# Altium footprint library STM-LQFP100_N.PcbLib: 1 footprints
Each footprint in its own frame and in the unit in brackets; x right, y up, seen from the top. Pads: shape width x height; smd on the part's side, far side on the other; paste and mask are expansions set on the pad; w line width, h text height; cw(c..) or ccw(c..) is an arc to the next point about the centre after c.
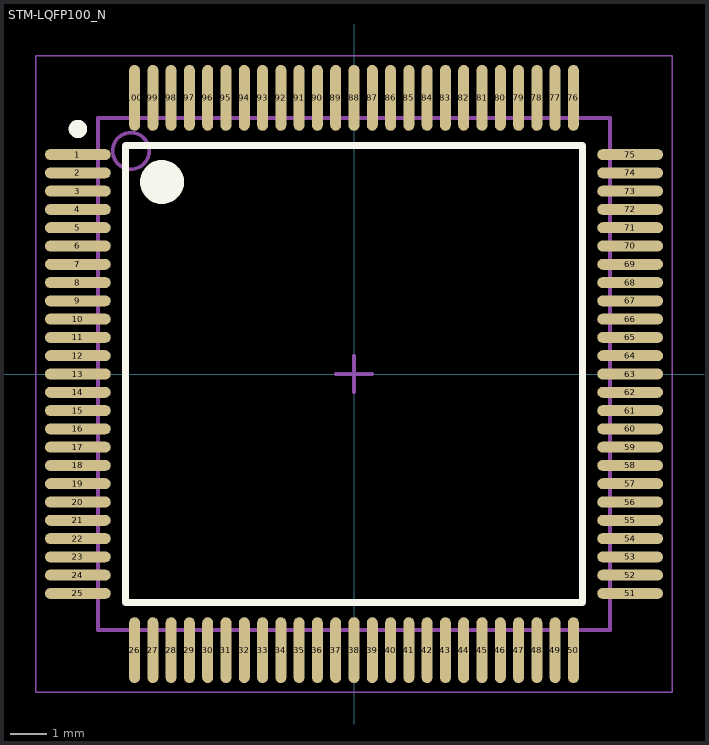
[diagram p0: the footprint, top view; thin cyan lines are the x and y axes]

## STM-LQFP100_N [mm] "Thin QFP, 100-Leads, Body 14x14mm, Pitch 0.5mm, IPC Medium Density"
height 1.6
pads (100):
  oval 1.8x0.3 smd: 1(-7.55,6) 2(-7.55,5.5) 3(-7.55,5) 4(-7.55,4.5) 5(-7.55,4) 6(-7.55,3.5) 7(-7.55,3) 8(-7.55,2.5) 9(-7.55,2) 10(-7.55,1.5) 11(-7.55,1) 12(-7.55,0.5) 13(-7.55,0) 14(-7.55,-0.5) 15(-7.55,-1) 16(-7.55,-1.5) 17(-7.55,-2) 18(-7.55,-2.5) 19(-7.55,-3) 20(-7.55,-3.5) 21(-7.55,-4) 22(-7.55,-4.5) 23(-7.55,-5) 24(-7.55,-5.5) 25(-7.55,-6) 51(7.55,-6) 52(7.55,-5.5) 53(7.55,-5) 54(7.55,-4.5) 55(7.55,-4) 56(7.55,-3.5) 57(7.55,-3) 58(7.55,-2.5) 59(7.55,-2) 60(7.55,-1.5) 61(7.55,-1) 62(7.55,-0.5) 63(7.55,0) 64(7.55,0.5) 65(7.55,1) 66(7.55,1.5) 67(7.55,2) 68(7.55,2.5) 69(7.55,3) 70(7.55,3.5) 71(7.55,4) 72(7.55,4.5) 73(7.55,5) 74(7.55,5.5) 75(7.55,6)
  oval 0.3x1.8 smd: 26(-6,-7.55) 27(-5.5,-7.55) 28(-5,-7.55) 29(-4.5,-7.55) 30(-4,-7.55) 31(-3.5,-7.55) 32(-3,-7.55) 33(-2.5,-7.55) 34(-2,-7.55) 35(-1.5,-7.55) 36(-1,-7.55) 37(-0.5,-7.55) 38(0,-7.55) 39(0.5,-7.55) 40(1,-7.55) 41(1.5,-7.55) 42(2,-7.55) 43(2.5,-7.55) 44(3,-7.55) 45(3.5,-7.55) 46(4,-7.55) 47(4.5,-7.55) 48(5,-7.55) 49(5.5,-7.55) 50(6,-7.55) 76(6,7.55) 77(5.5,7.55) 78(5,7.55) 79(4.5,7.55) 80(4,7.55) 81(3.5,7.55) 82(3,7.55) 83(2.5,7.55) 84(2,7.55) 85(1.5,7.55) 86(1,7.55) 87(0.5,7.55) 88(0,7.55) 89(-0.5,7.55) 90(-1,7.55) 91(-1.5,7.55) 92(-2,7.55) 93(-2.5,7.55) 94(-3,7.55) 95(-3.5,7.55) 96(-4,7.55) 97(-4.5,7.55) 98(-5,7.55) 99(-5.5,7.55) 100(-6,7.55)
Top Overlay:
  circle w0.6: c-5.25,5.25 r0.3
  circle w0.25: c-7.55,6.7 r0.125
  lines w0.2: -6.25,-6.25 6.25,-6.25 6.25,6.25 -6.25,6.25 -6.25,-6.25
Mechanical 13:
  circle w0.1: c-6.1,6.1 r0.5
  lines w0.1: -7,-7 7,-7 7,7 -7,7 -7,-7
Mechanical 15:
  lines w0.05: -8.7,-8.7 8.7,-8.7 8.7,8.7 -8.7,8.7 -8.7,-8.7
  lines w0.1: -0.5,0 0.5,0 ; 0,-0.5 0,0.5
Mechanical 31:
  lines w0.102: -7,-7 7,-7 7,7 -7,7 -7,-7
  text ".Comment" at -4.572,2.921 h0.76
  text ".Designator" at -4.572,4.191 h0.76
3D body "User Library-TQFP100_Grid_0_5.STEP": height 1.2, standoff 0, extent -8,-8 8,8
